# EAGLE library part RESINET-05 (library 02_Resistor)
Resistor Network(5) 5 peaces
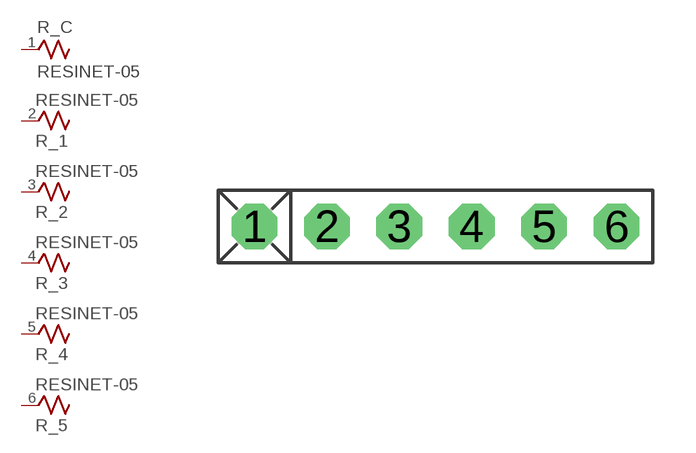
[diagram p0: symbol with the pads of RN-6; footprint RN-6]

Designator prefix R; gates _C=RESINET-COM _1=RESINET-X _2=RESINET-X _3=RESINET-X _4=RESINET-X _5=RESINET-X

## RESINET-05  [RN-6]
1  _C:1  pas
2  _1:1  pas
3  _2:1  pas
4  _3:1  pas
5  _4:1  pas
6  _5:1  pas

## Footprint RN-6 (pad centres in mm)
Resistor Network(5) 5 peaces
drill 0.813 pad 1.6 octagon: 1 -6.35,0; 2 -3.81,0; 3 -1.27,0; 4 1.27,0; 5 3.81,0; 6 6.35,0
